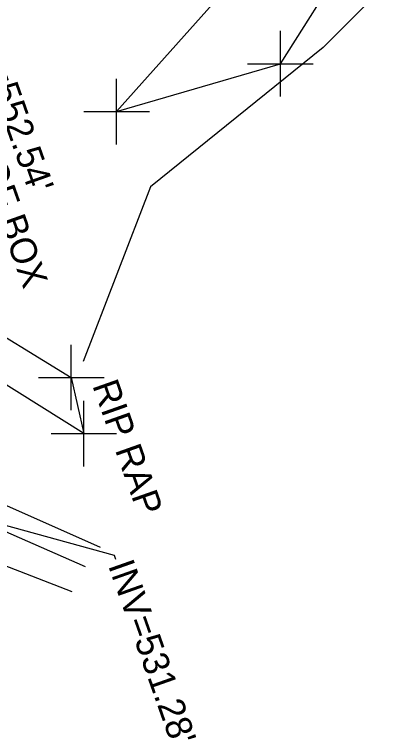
# Model space of a CAD drawing. Extents: x 2004847 to 2009016, y 1134161 to 1140101.
# Drawn here: x 2007994.5 to 2008054.1, y 1138990.4 to 1139100.8 of the extents above; entities that cross this region are included whole.
import ezdxf

# ---------------------------------------------------------------- set-up
doc = ezdxf.new("R2010")
doc.units = 0
for name, color, linetype in [('RD_EX_DR_Inlet_txCode', 7, 'Continuous'), ('RD_EX_DV_Prop_txCode', 7, 'Continuous'), ('RD_EX_H2O', 7, 'Continuous'), ('RD_EX_Misc', 7, 'Continuous'), ('RD_EX_VEG', 7, 'Continuous'), ('RD_Sketch3', 7, 'Continuous')]:
    doc.layers.add(name, color=color, linetype=linetype)

msp = doc.modelspace()

# ---------------------------------------------------------------- linework, layer by layer
at = {"layer": 'RD_EX_DR_Inlet_txCode'}
msp.add_lwpolyline([(2007968.12, 1139029.89), (2008009.69, 1139018.47), (2008009.91, 1139017.86)], dxfattribs=at)
at = {"layer": 'RD_EX_DV_Prop_txCode'}
for p, q in [((2008035.04, 1139088.32), (2008035.04, 1139098.32)), ((2008030.04, 1139093.32), (2008040.04, 1139093.32)), ((2008010.06, 1139081.05), (2008010.06, 1139091.05)), ((2008005.06, 1139086.05), (2008015.06, 1139086.05)), ((2008003.14, 1139040.53), (2008003.14, 1139050.53)), ((2007998.14, 1139045.53), (2008008.14, 1139045.53)), ((2008005.06, 1139031.99), (2008005.06, 1139041.99)), ((2008000.06, 1139036.99), (2008010.06, 1139036.99))]:
    msp.add_line(p, q, dxfattribs=at)
at = {"layer": 'RD_EX_H2O'}
for p, q in [((2008007.6, 1139019.61), (2007976.23, 1139033.48)), ((2008005.33, 1139016.68), (2007974.83, 1139030.04)), ((2008003.27, 1139012.86), (2007974.05, 1139024.24))]:
    msp.add_line(p, q, dxfattribs=at)
at = {"layer": 'RD_EX_Misc'}
for points in [[(2008035.04, 1139093.32), (2008045.15, 1139109.3), (2008034.11, 1139113.01), (2008010.06, 1139086.05), (2008035.04, 1139093.32)], [(2008005.06, 1139036.99), (2007988.38, 1139047.42), (2007980.48, 1139047.71), (2007972.23, 1139050.22), (2007986.88, 1139055.5), (2008003.14, 1139045.53), (2008005.06, 1139036.99)]]:
    msp.add_lwpolyline(points, dxfattribs=at)
at = {"layer": 'RD_EX_VEG'}
msp.add_lwpolyline([(2008089.91, 1139119.04), (2008067.01, 1139121.21), (2008041.57, 1139095.83), (2008015.2, 1139074.58), (2008004.96, 1139047.99)], dxfattribs=at)

# ---------------------------------------------------------------- texts
at = {"layer": 'RD_EX_DR_Inlet_txCode'}
for s, p in [("TOP=552.54'", (2007986.32, 1139102.98)), ('BOTTOM OF BOX', (2007981.05, 1139100.9)), ("INV=531.28'", (2008008.72, 1139016.9))]:
    msp.add_text(s, height=4, rotation=289.4494, dxfattribs=at).set_placement(p)
at = {"layer": 'RD_Sketch3'}
msp.add_text('RIP RAP', height=4, rotation=289.4494, dxfattribs=at).set_placement((2008006.32, 1139044.33))

doc.saveas('drawing.dxf')
